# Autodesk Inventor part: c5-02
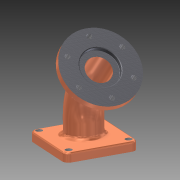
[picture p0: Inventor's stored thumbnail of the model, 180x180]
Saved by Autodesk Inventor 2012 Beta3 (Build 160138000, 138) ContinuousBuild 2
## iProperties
Created: 2010-11
Part Number: c5-02
Material: Cast Iron
Document SubType Name: Modeling
Designer: Beta-8540w
Density: 7.25 g/cm^3
Mass: 3065.97 g
Surface Area: 919.492 cm^2
Volume: 422.893 cm^3
Author: Beta-8540w
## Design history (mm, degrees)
sketch "Sketch1"
  geometry: L1 (55, 55)-(55, -55); L2 (55, -55)-(-55, -55); L3 (-55, -55)-(-55, 55); L4 (-55, 55)-(55, 55); C1 r 28 at (0, 0); C2 r 20 at (0, 0); 2 further points
  constraints: 8 end point, 3 coincident, 2 centre point, 1 horizontal, 9 other
  dimensions: "d0" = 110 distance of L3.end L1.start; "d8" = 8 radial gap between concentric circles of C1 C2; "d17" = 40 diameter of C2
extrude "Extrusion1" new body sketch "Sketch1" distance "d1" = 15; taper "d2" = 0 deg
sketch "Sketch2"
  geometry: L1 (0, 0)-(0, 40); L2 (-23.431, 96.569)-(-55.251, 128.388); A1 r 80 centre (-80, 40) between (0, 40) and (-23.431, 96.569)
  constraints: 4 end point, 2 point on circle, 2 tangent, 1 centre point, 1 vertical
  dimensions: "d3" = 40 distance of L1.start L1.end; "d4" = 45 distance of L2.start L2.end; "d5" = 135 deg angle of L1 L2; "d6" = 80 radius of A1
workplane "Work Plane1"
sketch "Sketch3"
  geometry: C1 r 60 at (0, 0); 2 further points
  constraints: 1 centre point, 1 coincident
  dimensions: "d9" = 120 diameter of C1
extrude "Extrusion2" join sketch "Sketch3" distance "d10" = 14; taper "d11" = 0 deg
sweep "Sweep1" dims "d12" = 0
sweep "Sweep2" dims "d13" = 0
fillet "Fillet1" dims "d14" = 10, "d15" = 8, "d16" = 4
hole "Hole1" diameter "d20" = 11; stored, may be unused: countersink angle "d24" = 90 deg, drill point angle "d26" = 118 deg; dims "d18" = 10, "d19" = 10, "d21" = 6, "d22" = 20, "d23" = 2, "d25" = 8
hole "Hole2" diameter "d29" = 11; stored, may be unused: countersink angle "d33" = 90 deg, drill point angle "d35" = 118 deg; dims "d27" = 10, "d28" = 10, "d30" = 6, "d31" = 20, "d32" = 2, "d34" = 8
hole "Hole3" diameter "d38" = 11; stored, may be unused: countersink angle "d42" = 90 deg, drill point angle "d44" = 118 deg; dims "d36" = 10, "d37" = 10, "d39" = 6, "d40" = 20, "d41" = 2, "d43" = 8
hole "Hole4" diameter "d47" = 11; stored, may be unused: countersink angle "d51" = 90 deg, drill point angle "d53" = 118 deg; dims "d45" = 10, "d46" = 10, "d48" = 6, "d49" = 20, "d50" = 2, "d52" = 8
sketch "Sketch4" dims "d54" = 95
  geometry: L1 (0, 0)-(0, 47.5); C1 r 60 at (0, 0) reference; C2 r 20 at (0, 0) reference; 8 further points
  constraints: 2 coincident, 2 end point, 1 vertical, 1 vertical alignment, 9 other
  dimensions: "d79" = 360 deg dimension on C1.centre L1.end (derived)
hole "Hole5" sketch "Sketch4" at (0, 47.5), (-41.136, 23.75), (-41.136, -23.75), (0, -47.5), (41.136, -23.75), (41.136, 23.75) diameter "d55" = 8.376; stored, may be unused: countersink angle "d59" = 90 deg, drill point angle "d61" = 118 deg; dims "d56" = 6, "d57" = 20, "d58" = 2, "d60" = 8
sketch "Sketch5"
  geometry: C1 r 60 at (0, 0) reference; C2 r 30 at (0, 0); 1 further point
  constraints: 1 centre point, 1 coincident
  dimensions: "d62" = 60 diameter of C2
extrude "Extrusion3" cut sketch "Sketch5" distance "d63" = 8; taper "d64" = 0 deg
sketch "Sketch6"
  geometry: C1 r 20 at (0, 0) reference; C2 r 30 at (0, 0); C3 r 33 at (0, 0)
  constraints: 2 centre point, 1 coincident
  dimensions: "d65" = 60 diameter of C2; "d66" = 3 radial gap between concentric circles of C3 C2
extrude "Extrusion4" cut sketch "Sketch6" distance "d67" = 3; taper "d68" = 0 deg
fillet "Fillet2" dims "d69" = 0.5
chamfer "Chamfer1" distance "d70" = 2; stored, may be unused: second distance "d71" = 2, angle "d72" = 45 deg
chamfer "Chamfer2" distance "d73" = 1; stored, may be unused: second distance "d74" = 2, angle "d75" = 45 deg
fillet "Fillet3" dims "d76" = 0.5
body "Solid1"
